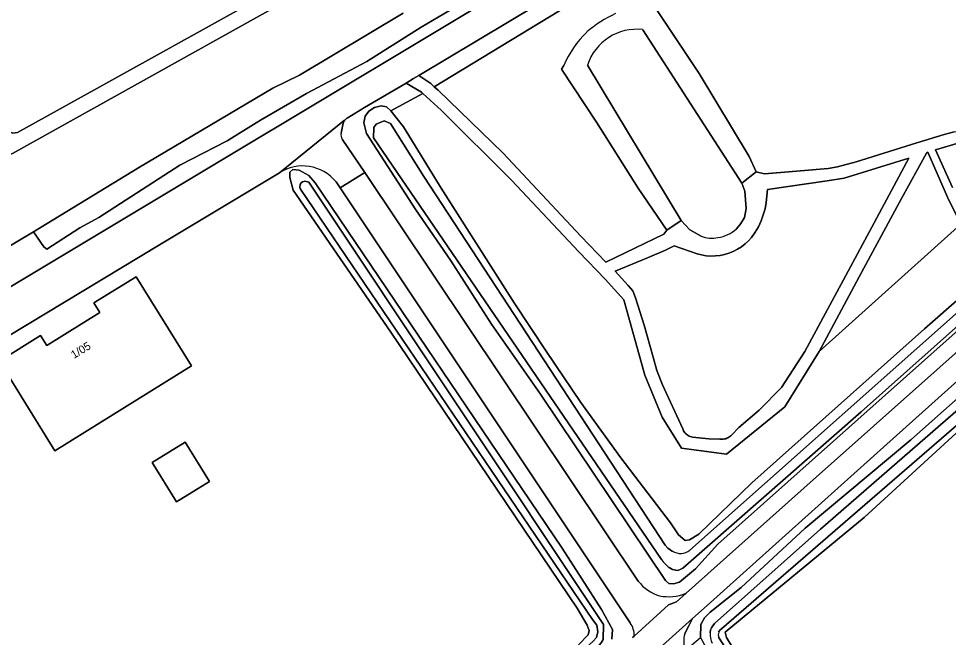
# Model space of a CAD drawing. Extents: x 162788 to 163838, y 385791 to 386523.
# Drawn here: x 163202.2 to 163318.3, y 386166.7 to 386243.9 of the extents above; entities that cross this region are included whole.
import ezdxf

# ---------------------------------------------------------------- set-up
doc = ezdxf.new("R2010")
doc.units = 0
for name, color, linetype in [('IMGEO_Erf', 7, 'Continuous'), ('IMGEO_Gemengd_bos', 7, 'Continuous'), ('IMGEO_Groenvoorziening', 7, 'Continuous'), ('IMGEO_Meer_plas_ven_vijver', 7, 'Continuous'), ('IMGEO_Oever', 7, 'Continuous'), ('IMGEO_Pand', 7, 'Continuous'), ('IMGEO_Pand_nummerreeks', 7, 'Continuous'), ('IMGEO_Rijbaan_lokaal_gesloten', 7, 'Continuous'), ('IMGEO_Rijbaan_lokaal_onverhard', 7, 'Continuous'), ('IMGEO_Rijbaan_lokaal_open', 7, 'Continuous'), ('IMGEO_Voetpad_halfverhard', 7, 'Continuous'), ('IMGEO_Waterloop', 7, 'Continuous'), ('IMGEO_Woonerf_open', 7, 'Continuous')]:
    doc.layers.add(name, color=color, linetype=linetype)

msp = doc.modelspace()

# ---------------------------------------------------------------- linework, layer by layer
at = {"layer": 'IMGEO_Erf'}
for points in [[(163192.64, 386244.3), (163200.49, 386230.52), (163200.89, 386229.9), (163201.46, 386229.64), (163202.05, 386229.7), (163238.52, 386250)], [(163234.75, 386224.68), (163219.8, 386215.69), (163191.37, 386198.58)], [(163272.09, 386165.77), (163273.33, 386167), (163273.43, 386167.56), (163273.21, 386168.2), (163271.93, 386170.32), (163248.69, 386204.78), (163236.48, 386222.54), (163236.06, 386224.12), (163236.06, 386224.76), (163236.42, 386225.12), (163237.21, 386225.02), (163238.43, 386224.34), (163239.23, 386223.44), (163270.07, 386177.82), (163274.97, 386170.16), (163276.37, 386167.66), (163276.27, 386166.44)], [(163278.57, 386168.48), (163242.34, 386222.83), (163241.83, 386223.56)], [(163278.85, 386166.67), (163279.05, 386166.85)]]:
    msp.add_lwpolyline(points, dxfattribs=at)
for points in [[(163206.71, 386189.99), (163199.77, 386201.17), (163204.94, 386204.39), (163205.71, 386203.14), (163212.34, 386207.26), (163211.6, 386208.44), (163216.87, 386211.71), (163223.77, 386200.58)], [(163218.88, 386188.5), (163222.99, 386191.06), (163226.04, 386186.16), (163221.92, 386183.6)]]:
    msp.add_lwpolyline(points, close=True, dxfattribs=at)
for centre, radius, start, end in [((163237.66, 386220.15), 5.39, 39.3459, 122.6739), ((163276.46, 386166.97), 2.6, 357.4335, 35.6423)]:
    msp.add_arc(centre, radius, start, end, dxfattribs=at)
at = {"layer": 'IMGEO_Gemengd_bos'}
for points in [[(163304.75, 386266.14), (163296.27, 386260.98), (163285.45, 386254.48), (163254.1, 386235.44), (163254.59, 386235), (163262.7, 386227.16), (163272.38, 386216.79), (163275.53, 386213.52), (163282.75, 386217.01), (163283.13, 386217.51), (163279.55, 386222.75), (163274.35, 386231.03), (163270, 386237.61), (163270.26, 386238.07)], [(163280.54, 386245.44), (163281.58, 386245.44), (163287.17, 386237.08), (163293.43, 386226.72), (163294.29, 386224.79), (163295.35, 386224.54), (163299.83, 386224.95), (163303.29, 386225.23), (163304.46, 386225.42), (163306.79, 386226.04), (163314.36, 386228.41), (163317.79, 386229.48), (163319.03, 386229.8), (163320.38, 386230.07), (163323.55, 386230.6), (163331.22, 386231.89), (163311.63, 386264.44)], [(163319.84, 386218.29), (163302.17, 386202.38), (163297.88, 386195.47), (163290.61, 386189.54), (163284.97, 386190.31), (163282.54, 386194.16), (163280.39, 386199.43), (163277.77, 386208.82), (163275.43, 386211.39), (163272.16, 386214.81), (163263.75, 386223.77), (163254.97, 386232.49), (163252.67, 386234.58), (163248.69, 386232.43), (163250.27, 386230.43), (163254.95, 386222.79), (163264.06, 386208.45), (163268.06, 386202.41), (163272.42, 386195.99), (163277.41, 386189.09), (163283.61, 386180.97), (163284.59, 386179.47), (163285.43, 386178.77), (163285.99, 386178.87), (163287.15, 386179.57), (163293.77, 386185.98), (163315.3, 386205.22), (163325.04, 386213.73)]]:
    msp.add_lwpolyline(points, dxfattribs=at)
msp.add_lwpolyline([(163300.39, 386202.38), (163305.79, 386212.4), (163308.76, 386217.91), (163313.36, 386226.51), (163305.3, 386224), (163303.17, 386223.69), (163295.73, 386222.61), (163295.54, 386220.98), (163295.4, 386220.19), (163295.19, 386219.42), (163294.92, 386218.68), (163294.58, 386217.96), (163294.18, 386217.27), (163293.73, 386216.61), (163293.33, 386216.19), (163292.91, 386215.8), (163292.45, 386215.45), (163291.96, 386215.14), (163291.44, 386214.88), (163290.9, 386214.66), (163290.35, 386214.49), (163289.78, 386214.38), (163289.2, 386214.31), (163288.62, 386214.3), (163288.05, 386214.34), (163287.48, 386214.43), (163286.91, 386214.57), (163284.05, 386215.56), (163282.98, 386215.02), (163280.72, 386214.09), (163276.69, 386212.4), (163278.3, 386210.61), (163278.88, 386209.95), (163279.21, 386209.07), (163280.3, 386205.66), (163281.45, 386201.66), (163281.91, 386200), (163282.6, 386198.22), (163285.13, 386192.73), (163285.18, 386192.6), (163285.24, 386192.48), (163285.31, 386192.36), (163285.4, 386192.24), (163285.49, 386192.14), (163285.59, 386192.05), (163285.7, 386191.96), (163285.82, 386191.89), (163285.94, 386191.82), (163286.07, 386191.77), (163286.21, 386191.73), (163286.34, 386191.7), (163288.39, 386191.46), (163289.74, 386191.44), (163289.89, 386191.43), (163290.04, 386191.42), (163290.19, 386191.43), (163290.34, 386191.46), (163290.49, 386191.49), (163290.63, 386191.54), (163290.77, 386191.6), (163290.9, 386191.67), (163291.02, 386191.76), (163291.14, 386191.85), (163291.24, 386191.96), (163292.14, 386192.89), (163294.67, 386195.06), (163297.47, 386197.87)], close=True, dxfattribs=at)
for centre, radius, start, end in [((163283.46, 386230.07), 15.98, 114.8683, 130.2264), ((163282.31, 386232.89), 13.11, 134.3562, 156.7334)]:
    msp.add_arc(centre, radius, start, end, dxfattribs=at)
at = {"layer": 'IMGEO_Groenvoorziening'}
for points in [[(163179.35, 386244.77), (163178.47, 386243.33), (163176.88, 386240.52), (163176.56, 386238.97), (163189.54, 386209.99), (163189.87, 386209.57), (163190.23, 386209.18), (163190.62, 386208.82), (163191.04, 386208.5), (163191.49, 386208.22), (163191.96, 386207.98), (163192.45, 386207.78), (163192.96, 386207.62), (163193.48, 386207.51), (163194, 386207.45), (163194.53, 386207.43), (163195.06, 386207.46), (163195.59, 386207.53), (163196.11, 386207.65), (163196.61, 386207.82), (163197.1, 386208.03), (163227.75, 386226.41), (163301.9, 386270.89)], [(163264.5, 386250), (163252.47, 386242.88), (163245.67, 386238.59), (163238.16, 386234.59), (163232.38, 386231.28), (163228.24, 386228.66), (163222.34, 386225.65), (163212.19, 386219.1), (163209.85, 386217.82), (163205.69, 386215.15), (163205.33, 386215.45), (163204.03, 386217.31), (163199.93, 386214.86), (163198.97, 386214.25), (163197.24, 386214.45), (163192.32, 386222.89)], [(163374.94, 386248.38), (163355.39, 386230.89), (163345.19, 386221.76), (163339.87, 386217), (163325.04, 386203.73), (163310.61, 386190.82), (163288.16, 386170.66), (163286.36, 386169.05), (163285.91, 386168.22), (163285.63, 386167.66), (163285.37, 386167.13)], [(163256.12, 386213.77), (163251.79, 386220.05), (163245.65, 386229.61), (163245.31, 386230.91), (163245.45, 386231.77), (163245.93, 386232.37), (163246.63, 386232.85), (163247.47, 386233.07), (163248.13, 386232.93), (163248.69, 386232.43), (163252.67, 386234.58), (163252.49, 386234.75), (163250.59, 386235.88), (163245.4, 386232.86), (163243.2, 386231.52)], [(163242.71, 386230.9), (163242.46, 386229.64)], [(163242.6, 386228.88), (163245.44, 386224.72), (163279.57, 386173.72)], [(163319.65, 386228.42), (163316.7, 386227.56), (163318.83, 386222.84)], [(163321.8, 386207.09), (163289.51, 386178.31), (163286.71, 386175.23), (163284.71, 386173.57), (163283.97, 386173.37), (163283.41, 386173.43), (163282.99, 386173.79), (163267.36, 386197.05), (163261.24, 386205.77), (163256.12, 386213.77)], [(163285.54, 386172.19), (163301.05, 386186.01), (163332.67, 386214.15)], [(163313.6, 386191.33), (163322.88, 386199.58), (163324.21, 386201.04), (163325.71, 386202.34), (163328.64, 386204.04)], [(163285.42, 386165.06), (163287.36, 386166.66), (163287.39, 386168.29), (163287.86, 386169.13), (163288.55, 386169.85), (163292.44, 386172.89), (163300.42, 386180.32), (163313.6, 386191.33)]]:
    msp.add_lwpolyline(points, dxfattribs=at)
for points in [[(163285.45, 386254.48), (163282.9, 386255.22), (163267.08, 386245.73), (163252.17, 386236.84), (163253.66, 386235.82), (163254.1, 386235.44)], [(163302.17, 386202.38), (163319.84, 386218.29), (163318.2, 386221.65), (163315.74, 386227.25), (163315.55, 386227.15), (163312.43, 386221.46), (163307.46, 386212.25)], [(163351.42, 386170.99), (163330.97, 386202.08), (163330.35, 386201.71), (163325.73, 386197.38), (163323.73, 386195.92), (163321.71, 386194.12), (163319.76, 386192.64), (163307.78, 386181.66), (163290.44, 386167.33), (163290.58, 386166.67), (163292.7, 386163.19), (163298.6, 386154.45), (163302.55, 386148.89), (163315.83, 386127.93), (163319.34, 386122.66), (163322.46, 386118.35), (163322.79, 386117.68), (163363.42, 386149.31), (163364.28, 386149.43), (163365.11, 386149)]]:
    msp.add_lwpolyline(points, close=True, dxfattribs=at)
for centre, radius, start, end in [((163243.94, 386230.43), 1.31, 141.977, 159.3233), ((163243.89, 386230.46), 1.26, 123.2143, 141.8238), ((163243.4, 386229.42), 0.966, 166.8322, 214.3438), ((163283.65, 386176.76), 5.09, 216.7808, 253.8244), ((163283.37, 386177.46), 5.7, 258.3962, 292.3079), ((163288.97, 386166.18), 3.72, 165.2783, 197.6522)]:
    msp.add_arc(centre, radius, start, end, dxfattribs=at)
at = {"layer": 'IMGEO_Meer_plas_ven_vijver'}
for points in [[(163291.82, 386217.7), (163292.4, 386218.36), (163292.83, 386219.12), (163293.06, 386220.23), (163292.89, 386222.41), (163292.5, 386223.4), (163280.15, 386242.56)], [(163273.23, 386238.11), (163284.93, 386218.74)], [(163284.93, 386218.74), (163286, 386217.57), (163287.41, 386216.78)]]:
    msp.add_lwpolyline(points, dxfattribs=at)
for centre, radius, start, end in [((163279.38, 386236.15), 6.46, 83.1741, 162.3256), ((163288.92, 386220.92), 4.35, 278.0002, 312.0036), ((163288.71, 386219.91), 3.39, 247.4748, 283.8564)]:
    msp.add_arc(centre, radius, start, end, dxfattribs=at)
at = {"layer": 'IMGEO_Oever'}
for points in [[(163276.83, 386311.46), (163279.76, 386304.64), (163280.52, 386303.16), (163282.08, 386299.04), (163282.71, 386297.57), (163284.13, 386298.22), (163285.26, 386295.57), (163283.84, 386294.94), (163285.21, 386290.76), (163289.29, 386279.83), (163289.57, 386278.55), (163289.29, 386277.99), (163288.89, 386277.59), (163278.14, 386271.64), (163263.57, 386263.94), (163238.52, 386250), (163202.05, 386229.7), (163201.46, 386229.64), (163200.89, 386229.9), (163200.49, 386230.52), (163192.64, 386244.3)], [(163187.14, 386249.05), (163190.78, 386242.48), (163195.42, 386234.62), (163199.28, 386227.57), (163199.7, 386227.18), (163200.88, 386226.92), (163201.42, 386227.1), (163242.44, 386250)], [(163250.23, 386244.61), (163237.26, 386236.87), (163233.94, 386235.26), (163217.27, 386225.41), (163204.03, 386217.31), (163205.33, 386215.45), (163205.69, 386215.15), (163209.85, 386217.82), (163212.19, 386219.1), (163222.34, 386225.65), (163228.24, 386228.66), (163232.38, 386231.28), (163238.16, 386234.59), (163245.67, 386238.59), (163252.47, 386242.88), (163264.5, 386250)], [(163280.15, 386242.56), (163292.5, 386223.4), (163294.29, 386224.79), (163293.43, 386226.72), (163287.17, 386237.08), (163281.58, 386245.44)], [(163270.26, 386238.07), (163270, 386237.61), (163274.35, 386231.03), (163279.55, 386222.75), (163283.13, 386217.51), (163284.93, 386218.74), (163273.23, 386238.11)], [(163325.04, 386213.73), (163315.3, 386205.22), (163293.77, 386185.98), (163287.15, 386179.57), (163285.99, 386178.87), (163285.43, 386178.77), (163284.59, 386179.47), (163283.61, 386180.97), (163277.41, 386189.09), (163272.42, 386195.99), (163268.06, 386202.41), (163264.06, 386208.45), (163254.95, 386222.79), (163250.27, 386230.43), (163248.69, 386232.43), (163248.13, 386232.93), (163247.47, 386233.07), (163246.63, 386232.85), (163245.93, 386232.37), (163245.45, 386231.77), (163245.31, 386230.91), (163245.65, 386229.61), (163251.79, 386220.05), (163256.12, 386213.77), (163261.24, 386205.77), (163267.36, 386197.05), (163282.99, 386173.79), (163283.41, 386173.43), (163283.97, 386173.37), (163284.71, 386173.57), (163286.71, 386175.23), (163289.51, 386178.31), (163321.8, 386207.09)], [(163282.46, 386176.42), (163246.5, 386229.06), (163246.53, 386230.33), (163246.84, 386230.78), (163247.84, 386231.17), (163248.64, 386230.86), (163252.8, 386224.21), (163282.93, 386178.18)], [(163276.27, 386166.44), (163276.37, 386167.66), (163274.97, 386170.16), (163270.07, 386177.82), (163239.23, 386223.44), (163238.43, 386224.34), (163237.21, 386225.02), (163236.42, 386225.12), (163236.06, 386224.76), (163236.06, 386224.12), (163236.48, 386222.54), (163248.69, 386204.78), (163271.93, 386170.32), (163273.21, 386168.2), (163273.43, 386167.56), (163273.33, 386167), (163272.09, 386165.77)], [(163237.48, 386222.5), (163237.35, 386222.72), (163237.3, 386222.9), (163237.35, 386223.22), (163237.48, 386223.45), (163237.62, 386223.57), (163237.92, 386223.64), (163238.44, 386223.52), (163275.25, 386168.27), (163275.18, 386166.43), (163274.92, 386166.02), (163274.67, 386165.69), (163273.71, 386164.82), (163272.34, 386163.57), (163235.78, 386130.19), (163234.78, 386129.26), (163230.58, 386125.39), (163228.62, 386123.58)], [(163227.42, 386124.6), (163230.07, 386127.03), (163230.82, 386127.65), (163233.56, 386130.11), (163233.95, 386130.45), (163240.94, 386136.66), (163273.9, 386166.17), (163274.36, 386166.68), (163274.54, 386167.36), (163274.4, 386168.21), (163273.87, 386168.93), (163237.48, 386222.5)], [(163286.03, 386177.57), (163323.67, 386211.02), (163334.93, 386222.48), (163335.12, 386222.65), (163335.23, 386222.7), (163335.58, 386222.72), (163335.83, 386222.64), (163335.96, 386222.58), (163336.27, 386222.38), (163336.39, 386222.18), (163336.45, 386221.93), (163336.44, 386221.56), (163336.42, 386221.42), (163336.37, 386221.18), (163328.29, 386213.44), (163307.42, 386194.84), (163285.14, 386175.33), (163284.72, 386175.11), (163284.47, 386175.04), (163283.86, 386175.14), (163283.45, 386175.4)], [(163328.64, 386204.04), (163325.71, 386202.34), (163324.21, 386201.04), (163322.88, 386199.58), (163313.6, 386191.33), (163300.42, 386180.32), (163292.44, 386172.89), (163288.55, 386169.85), (163287.86, 386169.13), (163287.39, 386168.29), (163287.36, 386166.66), (163293.87, 386154.62), (163300.62, 386144.46), (163348.76, 386072.33), (163367.81, 386043.47), (163368.13, 386043.47)], [(163288.54, 386167.26), (163288.6, 386167.63), (163288.7, 386167.86), (163288.88, 386168.13), (163289.08, 386168.41), (163302.32, 386180.19), (163328.49, 386202.92)], [(163329.17, 386201.68), (163289.95, 386167.77), (163289.81, 386167.61), (163289.68, 386167.45), (163289.61, 386167.33)], [(163319.34, 386122.66), (163315.83, 386127.93), (163302.55, 386148.89), (163298.6, 386154.45), (163292.7, 386163.19), (163290.58, 386166.67), (163290.44, 386167.33), (163307.78, 386181.66), (163319.76, 386192.64)], [(163282.93, 386178.18), (163283.28, 386177.83), (163283.83, 386177.42)], [(163289.6, 386166.7), (163322.26, 386116.19), (163323.94, 386117.28), (163332.34, 386124.15), (163340.3, 386130.3), (163343.42, 386132.46), (163345.97, 386134.79), (163357.89, 386143.8), (163360.51, 386145.96), (163361.69, 386146.64), (163363.73, 386148.6), (163364, 386148.53), (163364.37, 386148.39)]]:
    msp.add_lwpolyline(points, dxfattribs=at)
for centre, radius, start, end in [((163283.46, 386230.07), 15.98, 114.8683, 130.2264), ((163282.31, 386232.89), 13.11, 134.3562, 156.7334), ((163279.38, 386236.15), 6.46, 83.1741, 162.3256), ((163284.82, 386179.18), 2.01, 240.5307, 306.9591), ((163286.59, 386179.41), 5.1, 215.9692, 231.9746), ((163290.7, 386166.99), 1.13, 162.4996, 194.3743), ((163292.54, 386167.39), 4.01, 181.7963, 201.1077)]:
    msp.add_arc(centre, radius, start, end, dxfattribs=at)
at = {"layer": 'IMGEO_Pand'}
for points in [[(163223.77, 386200.58), (163216.87, 386211.71), (163211.6, 386208.44), (163212.34, 386207.26), (163205.71, 386203.14), (163204.94, 386204.39), (163199.77, 386201.17), (163206.71, 386189.99)], [(163218.88, 386188.5), (163221.92, 386183.6), (163226.04, 386186.16), (163222.99, 386191.06)]]:
    msp.add_lwpolyline(points, close=True, dxfattribs=at)
at = {"layer": 'IMGEO_Rijbaan_lokaal_gesloten'}
for points in [[(163332.67, 386214.15), (163301.05, 386186.01), (163285.54, 386172.19), (163284.33, 386171.11), (163283.34, 386170.74), (163279.05, 386166.85), (163278.85, 386166.67)], [(163286.36, 386169.05), (163288.16, 386170.66), (163310.61, 386190.82), (163325.04, 386203.73)], [(163210.94, 386086.38), (163206.53, 386090.17), (163204.25, 386094.07), (163204.69, 386094.81), (163204.9, 386095.15), (163205.05, 386095.39), (163207.12, 386097.9), (163219.47, 386108.78), (163274.09, 386158.01), (163277.65, 386161.21), (163286.36, 386169.05)], [(163285.37, 386167.13), (163285.63, 386167.66), (163285.91, 386168.22), (163286.36, 386169.05), (163277.65, 386161.21)]]:
    msp.add_lwpolyline(points, dxfattribs=at)
msp.add_arc((163288.97, 386166.18), 3.72, 165.2783, 197.6522, dxfattribs=at)
at = {"layer": 'IMGEO_Rijbaan_lokaal_onverhard'}
for points in [[(163245.44, 386224.72), (163242.34, 386222.83), (163278.57, 386168.48)], [(163279.57, 386173.72), (163245.44, 386224.72)], [(163279.05, 386166.85), (163283.34, 386170.74), (163284.33, 386171.11), (163285.54, 386172.19)]]:
    msp.add_lwpolyline(points, dxfattribs=at)
for centre, radius, start, end in [((163283.65, 386176.76), 5.09, 216.7808, 253.8244), ((163283.37, 386177.46), 5.7, 258.3962, 292.3079), ((163276.46, 386166.97), 2.6, 357.4335, 35.6423)]:
    msp.add_arc(centre, radius, start, end, dxfattribs=at)
at = {"layer": 'IMGEO_Rijbaan_lokaal_open'}
for points in [[(163242.9, 386231.24), (163234.75, 386224.68)], [(163242.46, 386229.64), (163242.71, 386230.9)], [(163241.83, 386223.56), (163242.34, 386222.83), (163245.44, 386224.72), (163242.6, 386228.88)]]:
    msp.add_lwpolyline(points, dxfattribs=at)
for centre, radius, start, end in [((163243.94, 386230.43), 1.31, 141.977, 159.3233), ((163243.4, 386229.42), 0.966, 166.8322, 214.3438), ((163237.66, 386220.15), 5.39, 39.3459, 122.6739)]:
    msp.add_arc(centre, radius, start, end, dxfattribs=at)
at = {"layer": 'IMGEO_Voetpad_halfverhard'}
for points in [[(163254.1, 386235.44), (163253.66, 386235.82), (163252.17, 386236.84), (163251.52, 386236.45), (163250.59, 386235.88), (163252.49, 386234.75), (163252.67, 386234.58), (163254.97, 386232.49), (163263.75, 386223.77), (163272.16, 386214.81), (163275.43, 386211.39), (163277.77, 386208.82), (163280.39, 386199.43), (163282.54, 386194.16), (163284.97, 386190.31), (163290.61, 386189.54), (163297.88, 386195.47), (163302.17, 386202.38), (163307.46, 386212.25), (163312.43, 386221.46), (163315.55, 386227.15), (163315.74, 386227.25), (163318.2, 386221.65), (163319.84, 386218.29)], [(163287.41, 386216.78), (163286, 386217.57), (163284.93, 386218.74), (163283.13, 386217.51), (163282.75, 386217.01), (163275.53, 386213.52), (163272.38, 386216.79), (163262.7, 386227.16), (163254.59, 386235), (163254.1, 386235.44)], [(163319.03, 386229.8), (163317.79, 386229.48), (163314.36, 386228.41), (163306.79, 386226.04), (163304.46, 386225.42), (163303.29, 386225.23), (163299.83, 386224.95), (163295.35, 386224.54), (163294.29, 386224.79), (163292.5, 386223.4), (163292.89, 386222.41), (163293.06, 386220.23), (163292.83, 386219.12), (163292.4, 386218.36), (163291.82, 386217.7)], [(163318.83, 386222.84), (163316.7, 386227.56), (163319.65, 386228.42)]]:
    msp.add_lwpolyline(points, dxfattribs=at)
msp.add_lwpolyline([(163300.39, 386202.38), (163297.47, 386197.87), (163294.67, 386195.06), (163292.14, 386192.89), (163291.24, 386191.96), (163291.14, 386191.85), (163291.02, 386191.76), (163290.9, 386191.67), (163290.77, 386191.6), (163290.63, 386191.54), (163290.49, 386191.49), (163290.34, 386191.46), (163290.19, 386191.43), (163290.04, 386191.42), (163289.89, 386191.43), (163289.74, 386191.44), (163288.39, 386191.46), (163286.34, 386191.7), (163286.21, 386191.73), (163286.07, 386191.77), (163285.94, 386191.82), (163285.82, 386191.89), (163285.7, 386191.96), (163285.59, 386192.05), (163285.49, 386192.14), (163285.4, 386192.24), (163285.31, 386192.36), (163285.24, 386192.48), (163285.18, 386192.6), (163285.13, 386192.73), (163282.6, 386198.22), (163281.91, 386200), (163281.45, 386201.66), (163280.3, 386205.66), (163279.21, 386209.07), (163278.88, 386209.95), (163278.3, 386210.61), (163276.69, 386212.4), (163280.72, 386214.09), (163282.98, 386215.02), (163284.05, 386215.56), (163286.91, 386214.57), (163287.48, 386214.43), (163288.05, 386214.34), (163288.62, 386214.3), (163289.2, 386214.31), (163289.78, 386214.38), (163290.35, 386214.49), (163290.9, 386214.66), (163291.44, 386214.88), (163291.96, 386215.14), (163292.45, 386215.45), (163292.91, 386215.8), (163293.33, 386216.19), (163293.73, 386216.61), (163294.18, 386217.27), (163294.58, 386217.96), (163294.92, 386218.68), (163295.19, 386219.42), (163295.4, 386220.19), (163295.54, 386220.98), (163295.73, 386222.61), (163303.17, 386223.69), (163305.3, 386224), (163313.36, 386226.51), (163308.76, 386217.91), (163305.79, 386212.4)], close=True, dxfattribs=at)
for centre, radius, start, end in [((163288.92, 386220.92), 4.35, 278.0002, 312.0036), ((163288.71, 386219.91), 3.39, 247.4748, 283.8564)]:
    msp.add_arc(centre, radius, start, end, dxfattribs=at)
at = {"layer": 'IMGEO_Waterloop'}
for points in [[(163269.34, 386264.69), (163262.13, 386260.88), (163242.44, 386250), (163201.42, 386227.1), (163200.88, 386226.92), (163199.7, 386227.18), (163199.28, 386227.57), (163195.42, 386234.62), (163190.78, 386242.48), (163187.14, 386249.05), (163185.76, 386251.76), (163175.83, 386269.65)], [(163181.21, 386246.07), (163184.51, 386240.51), (163188.82, 386232.55), (163194.48, 386223.05), (163197.46, 386218.47), (163198.26, 386216.85), (163199.31, 386215.21), (163199.93, 386214.86), (163204.03, 386217.31), (163217.27, 386225.41), (163233.94, 386235.26), (163237.26, 386236.87), (163250.23, 386244.61)], [(163283.83, 386177.42), (163283.28, 386177.83), (163282.93, 386178.18), (163252.8, 386224.21), (163248.64, 386230.86), (163247.84, 386231.17), (163246.84, 386230.78), (163246.53, 386230.33), (163246.5, 386229.06)], [(163246.5, 386229.06), (163282.46, 386176.42)], [(163238.44, 386223.52), (163237.92, 386223.64), (163237.62, 386223.57), (163237.48, 386223.45), (163237.35, 386223.22), (163237.3, 386222.9), (163237.35, 386222.72), (163237.48, 386222.5), (163273.87, 386168.93), (163274.4, 386168.21), (163274.54, 386167.36), (163274.36, 386166.68), (163273.9, 386166.17), (163240.94, 386136.66), (163233.95, 386130.45), (163233.56, 386130.11), (163230.82, 386127.65), (163230.07, 386127.03), (163227.42, 386124.6)], [(163228.62, 386123.58), (163230.58, 386125.39), (163234.78, 386129.26), (163235.78, 386130.19), (163272.34, 386163.57), (163273.71, 386164.82), (163274.67, 386165.69), (163274.92, 386166.02), (163275.18, 386166.43), (163275.25, 386168.27), (163238.44, 386223.52)], [(163283.45, 386175.4), (163283.86, 386175.14), (163284.47, 386175.04), (163284.72, 386175.11), (163285.14, 386175.33), (163307.42, 386194.84), (163328.29, 386213.44), (163336.37, 386221.18), (163336.42, 386221.42), (163336.44, 386221.56), (163336.45, 386221.93), (163336.39, 386222.18), (163336.27, 386222.38), (163335.96, 386222.58), (163335.83, 386222.64), (163335.58, 386222.72), (163335.23, 386222.7), (163335.12, 386222.65), (163334.93, 386222.48), (163323.67, 386211.02), (163286.03, 386177.57)], [(163328.49, 386202.92), (163302.32, 386180.19), (163289.08, 386168.41), (163288.88, 386168.13), (163288.7, 386167.86), (163288.6, 386167.63), (163288.54, 386167.26)], [(163289.61, 386167.33), (163289.68, 386167.45), (163289.81, 386167.61), (163289.95, 386167.77), (163329.17, 386201.68)], [(163364.37, 386148.39), (163364, 386148.53), (163363.73, 386148.6), (163361.69, 386146.64), (163360.51, 386145.96), (163357.89, 386143.8), (163345.97, 386134.79), (163343.42, 386132.46), (163340.3, 386130.3), (163332.34, 386124.15), (163323.94, 386117.28), (163322.26, 386116.19), (163289.6, 386166.7)]]:
    msp.add_lwpolyline(points, dxfattribs=at)
for centre, radius, start, end in [((163284.82, 386179.18), 2.01, 240.5307, 306.9591), ((163286.59, 386179.41), 5.1, 215.9692, 231.9746), ((163290.7, 386166.99), 1.13, 162.4996, 194.3743), ((163292.54, 386167.39), 4.01, 181.7963, 201.1077)]:
    msp.add_arc(centre, radius, start, end, dxfattribs=at)
at = {"layer": 'IMGEO_Woonerf_open'}
for points in [[(163301.9, 386270.89), (163227.75, 386226.41), (163197.1, 386208.03), (163196.61, 386207.82), (163196.11, 386207.65), (163195.59, 386207.53), (163195.06, 386207.46), (163194.53, 386207.43), (163194, 386207.45), (163193.48, 386207.51), (163192.96, 386207.62), (163192.45, 386207.78), (163191.96, 386207.98), (163191.49, 386208.22), (163191.04, 386208.5), (163190.62, 386208.82), (163190.23, 386209.18), (163189.87, 386209.57), (163189.54, 386209.99), (163176.56, 386238.97), (163171.99, 386249.22)], [(163243.2, 386231.52), (163245.4, 386232.86), (163250.59, 386235.88), (163251.52, 386236.45), (163252.17, 386236.84), (163267.08, 386245.73)], [(163182.8, 386199.39), (163182.62, 386199.28), (163185.27, 386194.92), (163191.37, 386198.58), (163219.8, 386215.69), (163234.75, 386224.68), (163242.9, 386231.24)]]:
    msp.add_lwpolyline(points, dxfattribs=at)
msp.add_arc((163243.89, 386230.46), 1.26, 123.2143, 141.8238, dxfattribs=at)

# ---------------------------------------------------------------- texts
at = {"layer": 'IMGEO_Pand_nummerreeks'}
msp.add_text('1/05', height=1, rotation=31.5002, dxfattribs=at).set_placement((163209.1, 386201.44))

doc.saveas('drawing.dxf')
